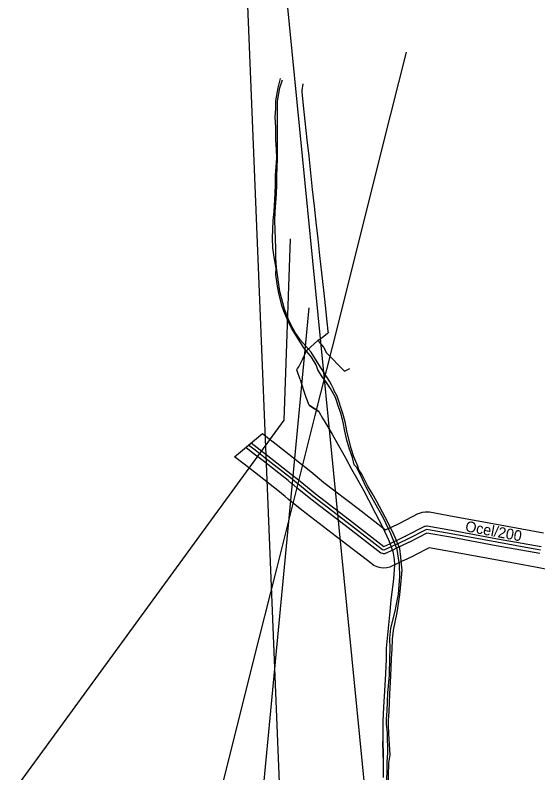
# Model space of a CAD drawing. Extents: x -555222 to -543220, y -1067119 to -1030889.
# Drawn here: x -550763 to -550174, y -1042854 to -1042000 of the extents above; entities that cross this region are included whole.
import ezdxf

# ---------------------------------------------------------------- set-up
doc = ezdxf.new("R2010")
doc.units = 0
for name, color, linetype in [('07_ELEKTRO', 7, 'Continuous'), ('07_OCH_P A POPISY TI', 7, 'Continuous'), ('07_PLYNOVOD', 7, 'Continuous'), ('07_SDĚLOVACÍ', 7, 'Continuous'), ('07_VODOVOD', 7, 'Continuous')]:
    doc.layers.add(name, color=color, linetype=linetype)

msp = doc.modelspace()

# ---------------------------------------------------------------- linework, layer by layer
at = {"layer": '07_ELEKTRO'}
msp.add_lwpolyline([(-550322.66, -1042042.04), (-550348.79, -1042146.16), (-550377.81, -1042262.02), (-550406.02, -1042374.27), (-550425.38, -1042451.48), (-550442.39, -1042519.12), (-550468.87, -1042624.23), (-550495.65, -1042731.01), (-550522.8, -1042839.41), (-550549.35, -1042945.71)], dxfattribs=at)
at = {"layer": '07_OCH_P A POPISY TI'}
for p, q in [((-550515.93, -1042497.96), (-550484.62, -1042471.7)), ((-550484.62, -1042471.7), (-550480.62, -1042474.85)), ((-550480.62, -1042474.85), (-550469.1, -1042483.81)), ((-550503.41, -1042487.46), (-550497.14, -1042482.21)), ((-550497.14, -1042482.21), (-550490.48, -1042487.45)), ((-550469.1, -1042483.81), (-550440.57, -1042506.13)), ((-550495.4, -1042493.75), (-550503.41, -1042487.46)), ((-550483.86, -1042502.73), (-550495.4, -1042493.75)), ((-550490.48, -1042487.45), (-550478.94, -1042496.43)), ((-550505.26, -1042506.35), (-550515.93, -1042497.96)), ((-550478.94, -1042496.43), (-550450.55, -1042518.63)), ((-550493.7, -1042515.35), (-550505.26, -1042506.35)), ((-550455.55, -1042524.89), (-550483.86, -1042502.73)), ((-550440.57, -1042506.13), (-550435.72, -1042510.08)), ((-550435.72, -1042510.08), (-550433.56, -1042511.84)), ((-550465.53, -1042537.39), (-550493.7, -1042515.35)), ((-550450.55, -1042518.63), (-550445.83, -1042522.48)), ((-550433.56, -1042511.84), (-550430.18, -1042514.59)), ((-550430.18, -1042514.59), (-550415.23, -1042526.81)), ((-550450.89, -1042528.68), (-550455.55, -1042524.89)), ((-550445.83, -1042522.48), (-550443.66, -1042524.25)), ((-550443.66, -1042524.25), (-550440.29, -1042526.99)), ((-550440.29, -1042526.99), (-550425.17, -1042539.35)), ((-550415.23, -1042526.81), (-550376.74, -1042556.36)), ((-550448.72, -1042530.45), (-550450.89, -1042528.68)), ((-550445.35, -1042533.19), (-550448.72, -1042530.45)), ((-550430.13, -1042545.63), (-550445.35, -1042533.19)), ((-550461, -1042541.08), (-550465.53, -1042537.39)), ((-550458.82, -1042542.86), (-550461, -1042541.08)), ((-550455.46, -1042545.59), (-550458.82, -1042542.86)), ((-550425.17, -1042539.35), (-550386.5, -1042569.04)), ((-550440.07, -1042558.17), (-550455.46, -1042545.59)), ((-550391.38, -1042575.38), (-550430.13, -1042545.63)), ((-550401.14, -1042588.06), (-550440.07, -1042558.17)), ((-550376.74, -1042556.36), (-550345.75, -1042580.31)), ((-550329.9, -1042572.79), (-550308.88, -1042562.08)), ((-550308.88, -1042562.08), (-550307.44, -1042561.35)), ((-550307.44, -1042561.35), (-550304.36, -1042560.36)), ((-550304.36, -1042560.36), (-550301.16, -1042559.88)), ((-550301.16, -1042559.88), (-550297.92, -1042559.92)), ((-550297.92, -1042559.92), (-550296.33, -1042560.2)), ((-550296.33, -1042560.2), (-550268.51, -1042565.1)), ((-550386.5, -1042569.04), (-550347.84, -1042598.91)), ((-550268.51, -1042565.1), (-550216.76, -1042574.55)), ((-550351.01, -1042606.58), (-550391.38, -1042575.38)), ((-550344.49, -1042579.69), (-550338.94, -1042577.12)), ((-550338.94, -1042577.12), (-550330.52, -1042573.09)), ((-550330.52, -1042573.09), (-550329.9, -1042572.79)), ((-550322.97, -1042587.22), (-550301.62, -1042576.34)), ((-550301.62, -1042576.34), (-550301.04, -1042576.04)), ((-550301.04, -1042576.04), (-550299.75, -1042575.85)), ((-550299.75, -1042575.85), (-550299.11, -1042575.96)), ((-550299.11, -1042575.96), (-550271.33, -1042580.85)), ((-550216.76, -1042574.55), (-550167.7, -1042583.52)), ((-550345.75, -1042580.31), (-550344.49, -1042579.69)), ((-550332.12, -1042591.59), (-550323.61, -1042587.52)), ((-550323.61, -1042587.52), (-550323.11, -1042587.28)), ((-550323.11, -1042587.28), (-550322.97, -1042587.22)), ((-550299.18, -1042584.07), (-550319.53, -1042594.44)), ((-550272.75, -1042588.73), (-550299.18, -1042584.07)), ((-550271.33, -1042580.85), (-550219.63, -1042590.28)), ((-550361.44, -1042618.74), (-550401.14, -1042588.06)), ((-550347.84, -1042598.91), (-550341.18, -1042595.9)), ((-550341.18, -1042595.9), (-550337.58, -1042594.12)), ((-550337.58, -1042594.12), (-550332.12, -1042591.59)), ((-550320.15, -1042594.73), (-550328.72, -1042598.83)), ((-550319.75, -1042594.54), (-550320.15, -1042594.73)), ((-550319.53, -1042594.44), (-550319.75, -1042594.54)), ((-550221.07, -1042598.16), (-550272.75, -1042588.73)), ((-550219.63, -1042590.28), (-550170.61, -1042599.26)), ((-550337.76, -1042603.14), (-550346.14, -1042606.92)), ((-550334.12, -1042601.34), (-550337.76, -1042603.14)), ((-550328.72, -1042598.83), (-550334.12, -1042601.34)), ((-550296.68, -1042600.76), (-550312.64, -1042608.89)), ((-550275.57, -1042604.48), (-550296.68, -1042600.76)), ((-550223.94, -1042613.89), (-550275.57, -1042604.48)), ((-550172.07, -1042607.12), (-550221.07, -1042598.16)), ((-550348.8, -1042607.15), (-550351.01, -1042606.58)), ((-550348.14, -1042607.32), (-550348.8, -1042607.15)), ((-550346.77, -1042607.21), (-550348.14, -1042607.32)), ((-550346.14, -1042606.92), (-550346.77, -1042607.21)), ((-550321.9, -1042613.3), (-550327.21, -1042615.77)), ((-550313.25, -1042609.17), (-550321.9, -1042613.3)), ((-550313.06, -1042609.07), (-550313.25, -1042609.17)), ((-550312.64, -1042608.89), (-550313.06, -1042609.07)), ((-550360.64, -1042619.35), (-550361.44, -1042618.74)), ((-550358.93, -1042620.42), (-550360.64, -1042619.35)), ((-550357.12, -1042621.31), (-550358.93, -1042620.42)), ((-550355.23, -1042622.01), (-550357.12, -1042621.31)), ((-550354.25, -1042622.26), (-550355.23, -1042622.01)), ((-550339.55, -1042621.5), (-550341.1, -1042622.21)), ((-550330.92, -1042617.6), (-550339.55, -1042621.5)), ((-550327.21, -1042615.77), (-550330.92, -1042617.6)), ((-550174.98, -1042622.86), (-550223.94, -1042613.89)), ((-550352.83, -1042622.63), (-550354.25, -1042622.26)), ((-550351.19, -1042623.06), (-550352.83, -1042622.63)), ((-550347.79, -1042623.35), (-550351.19, -1042623.06)), ((-550344.4, -1042623.06), (-550347.79, -1042623.35)), ((-550341.1, -1042622.21), (-550344.4, -1042623.06)), ((-550132.79, -1042630.77), (-550174.98, -1042622.86))]:
    msp.add_line(p, q, dxfattribs=at)
at = {"layer": '07_PLYNOVOD'}
msp.add_lwpolyline([(-550171.34, -1042603.19), (-550220.35, -1042594.22), (-550272.04, -1042584.79), (-550299.8, -1042579.9), (-550321.25, -1042590.83), (-550321.43, -1042590.91), (-550321.88, -1042591.13), (-550330.42, -1042595.21), (-550335.85, -1042597.73), (-550339.47, -1042599.52), (-550347.79, -1042603.28), (-550349.21, -1042602.91), (-550388.94, -1042572.21), (-550427.65, -1042542.49), (-550442.82, -1042530.09), (-550446.19, -1042527.35), (-550448.36, -1042525.58), (-550453.05, -1042521.76), (-550481.4, -1042499.58), (-550492.94, -1042490.6), (-550500.28, -1042484.83)], dxfattribs=at)
at = {"layer": '07_SDĚLOVACÍ'}
for p, q in [((-550531.78, -1041228.78), (-549789.42, -1048745)), ((-550437.35, -1043553.23), (-550531.78, -1041228.78))]:
    msp.add_line(p, q, dxfattribs=at)
for points in [[(-550469.09, -1042285.28), (-550471.35, -1042273.09), (-550472.7, -1042262.42), (-550473.29, -1042251.73), (-550472.39, -1042231.82), (-550471.23, -1042221.41), (-550470.36, -1042201.22), (-550469.83, -1042191.1), (-550469.72, -1042181.11), (-550469.19, -1042171.06), (-550468.5, -1042161.41), (-550468.58, -1042151.3), (-550469.37, -1042141.22), (-550469.55, -1042131.59), (-550469.65, -1042126.67), (-550470.24, -1042115.16), (-550469.66, -1042105.4), (-550469.64, -1042096.97), (-550466.97, -1042082.18), (-550464.4, -1042071.49)], [(-550464.89, -1042311.68), (-550468.62, -1042285.16), (-550469.54, -1042273.89), (-550469.36, -1042262.49), (-550469.9, -1042252.75), (-550470.63, -1042232.05), (-550470.19, -1042221.75), (-550468.68, -1042201.5), (-550468.45, -1042191.39), (-550468.26, -1042181.5), (-550467.88, -1042172.1), (-550467.44, -1042161.89), (-550467.61, -1042151.85), (-550467.7, -1042141.86), (-550467.75, -1042131.88), (-550467.79, -1042126.91), (-550467.6, -1042115.5), (-550467.67, -1042106.16), (-550467.64, -1042097.3), (-550464.93, -1042082.14), (-550462.14, -1042073)], [(-550439.11, -1042077.57), (-550440, -1042085.25), (-550440.13, -1042086.5), (-550438.53, -1042102.24), (-550436.65, -1042119.71), (-550434.45, -1042140.81), (-550432.31, -1042159.37), (-550430.34, -1042178.13), (-550428.46, -1042196.75), (-550426.33, -1042215.57), (-550424.36, -1042233.5), (-550422.13, -1042252.19), (-550420.22, -1042271), (-550418, -1042290.59), (-550415.85, -1042310.15), (-550413.95, -1042327.58), (-550411.9, -1042345.94), (-550410.71, -1042356.51), (-550410.63, -1042358.47), (-550411.36, -1042358.92), (-550415.35, -1042362.44), (-550420.18, -1042366.08), (-550420.56, -1042366.23)], [(-550421.47, -1042401.24), (-550422.33, -1042399.93), (-550424.08, -1042394.42), (-550429.23, -1042385.67), (-550437.83, -1042375.17), (-550441.73, -1042369.14), (-550451.65, -1042353.07), (-550456.21, -1042343.66), (-550460.44, -1042333.72), (-550462.52, -1042328.44), (-550465.86, -1042315.57), (-550467.57, -1042305.71), (-550469.39, -1042292.38), (-550469.09, -1042285.28)], [(-550429.51, -1042379.91), (-550441.58, -1042366.54), (-550447.59, -1042357.99), (-550452.72, -1042349), (-550455.04, -1042343.35), (-550459.84, -1042331.5), (-550464.89, -1042311.68)], [(-550442.19, -1042410.95), (-550442.61, -1042409.64), (-550445, -1042402.42), (-550445.68, -1042400.11), (-550445.06, -1042398.6), (-550443.45, -1042396.64), (-550439.17, -1042387.75), (-550435.57, -1042380), (-550434.74, -1042378.6), (-550421.73, -1042366.69)], [(-550434.74, -1042378.6), (-550421.73, -1042366.69)], [(-550420.56, -1042366.23), (-550421.73, -1042366.69)], [(-550421.73, -1042366.69), (-550420.76, -1042368.64), (-550415.81, -1042374.6), (-550412.58, -1042380.01), (-550412.65, -1042380.45)], [(-550417.5, -1042399.39), (-550418.96, -1042397.05), (-550429.51, -1042379.91)], [(-550412.65, -1042380.45), (-550391.92, -1042401.56), (-550386.1, -1042398.44)], [(-550340.5, -1042833.85), (-550342, -1042810.12), (-550342.67, -1042800.1), (-550342.48, -1042795.1), (-550341.91, -1042785.41), (-550340.94, -1042765.13), (-550339.88, -1042745.14), (-550339.09, -1042725.16), (-550338.55, -1042715.16), (-550338.02, -1042703.47), (-550336.83, -1042693.34), (-550332.76, -1042673.3), (-550329.62, -1042653.68), (-550327.69, -1042633.98), (-550327.18, -1042625.58), (-550327.92, -1042619.05), (-550328.51, -1042611.04), (-550329.74, -1042601.38), (-550337.33, -1042583.63), (-550346.1, -1042565.87), (-550355.52, -1042548.22), (-550360.7, -1042539.76), (-550365.85, -1042531.17), (-550372.64, -1042517.59), (-550375.87, -1042512.55), (-550377.11, -1042508.65), (-550381.74, -1042498.13), (-550384.54, -1042488.56), (-550389.28, -1042468.85), (-550391.42, -1042458.6), (-550394.06, -1042449.05), (-550400.43, -1042429.76), (-550403.59, -1042423.52), (-550404.56, -1042421.54), (-550406.75, -1042417.04), (-550409.13, -1042412.75), (-550417.5, -1042399.39)], [(-550378.64, -1042509.61), (-550381.12, -1042507.04), (-550383.12, -1042498.77), (-550386.31, -1042489.28), (-550389.55, -1042479.33), (-550391.8, -1042469.05), (-550393.66, -1042459.2), (-550395.75, -1042449.81), (-550398.99, -1042441.72), (-550402.33, -1042431.33), (-550407.92, -1042421.16), (-550413.17, -1042413.04), (-550417.2, -1042407.74), (-550421.47, -1042401.24)], [(-550442.19, -1042410.95), (-550438.74, -1042421.67), (-550435.62, -1042430.61), (-550432.44, -1042439.31), (-550431.9, -1042439.75), (-550431.44, -1042440.06), (-550420.89, -1042447.04), (-550416.72, -1042454.33), (-550411.03, -1042464.34), (-550406, -1042472.58), (-550398.9, -1042485.34), (-550391.49, -1042498.48), (-550390.66, -1042500), (-550384.24, -1042511.8), (-550377, -1042524.23), (-550370.45, -1042536.46), (-550365.01, -1042546.65), (-550356.97, -1042561.8), (-550349.22, -1042576.99), (-550342.28, -1042592.22), (-550337.77, -1042604.57), (-550336.23, -1042613.63), (-550335.65, -1042619.61), (-550336, -1042625.51), (-550336.95, -1042635.65), (-550337.69, -1042641.81), (-550339.69, -1042659.22), (-550341.06, -1042672.33), (-550345.12, -1042713.54), (-550345.21, -1042725.53), (-550346.04, -1042742.76), (-550347.07, -1042761.59), (-550348.09, -1042780.24), (-550348.79, -1042796.01), (-550348.76, -1042817.47), (-550348.75, -1042818.98), (-550348.69, -1042833.02), (-550348.69, -1042836.97), (-550348.7, -1042850.43), (-550348.61, -1042859.39)], [(-550420.89, -1042447.04), (-550431.44, -1042440.06)], [(-550340.47, -1042714.28), (-550340.95, -1042702.27), (-550339.88, -1042690.96), (-550334.96, -1042672), (-550333.01, -1042662.19), (-550331.32, -1042652.71), (-550330.59, -1042642.72), (-550329.75, -1042632.75), (-550330.06, -1042619.55), (-550331.33, -1042612.2), (-550332.92, -1042602.3), (-550339.92, -1042584.96), (-550348.32, -1042567.24), (-550358, -1042549.74), (-550362.78, -1042541.16), (-550367.7, -1042532.07), (-550374.09, -1042518.5), (-550378.64, -1042509.61)], [(-550356.48, -1042940.21), (-550354.24, -1042927.73), (-550351.44, -1042918.91), (-550349.52, -1042909.09), (-550349.4, -1042899.8), (-550348.37, -1042889.4), (-550346.91, -1042881.93), (-550344.23, -1042871.98), (-550344.21, -1042862.09), (-550344.07, -1042851.88), (-550343.85, -1042841.88), (-550343.22, -1042831.89), (-550343.56, -1042809.16), (-550344.74, -1042799.14), (-550344.65, -1042794.14), (-550343.87, -1042784.16), (-550343.31, -1042764.17), (-550341.25, -1042744.24), (-550341.06, -1042724.27), (-550340.47, -1042714.28)], [(-550348.69, -1042836.97), (-550348.69, -1042833.02), (-550348.75, -1042818.98)], [(-550342.74, -1042872.81), (-550342.08, -1042842.82), (-550340.5, -1042833.85)]]:
    msp.add_lwpolyline(points, dxfattribs=at)
at = {"layer": '07_VODOVOD'}
for points in [[(-551042.88, -1043255.35), (-550460.08, -1042456.84), (-550453.11, -1042252.45)], [(-550680.05, -1044068.39), (-550741.21, -1043925.77), (-550758.46, -1043772.18), (-550749.05, -1043629.57), (-550683.19, -1043477.54), (-550620.43, -1043319.91), (-550507.52, -1043124), (-550432.01, -1042330.28)]]:
    msp.add_lwpolyline(points, dxfattribs=at)

# ---------------------------------------------------------------- texts
at = {"layer": '07_OCH_P A POPISY TI'}
msp.add_text('Ocel/200', height=12, rotation=349.66102, dxfattribs=at).set_placement((-550256.71, -1042581.86))

doc.saveas('drawing.dxf')
